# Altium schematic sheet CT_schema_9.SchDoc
size 391 x 238 mm
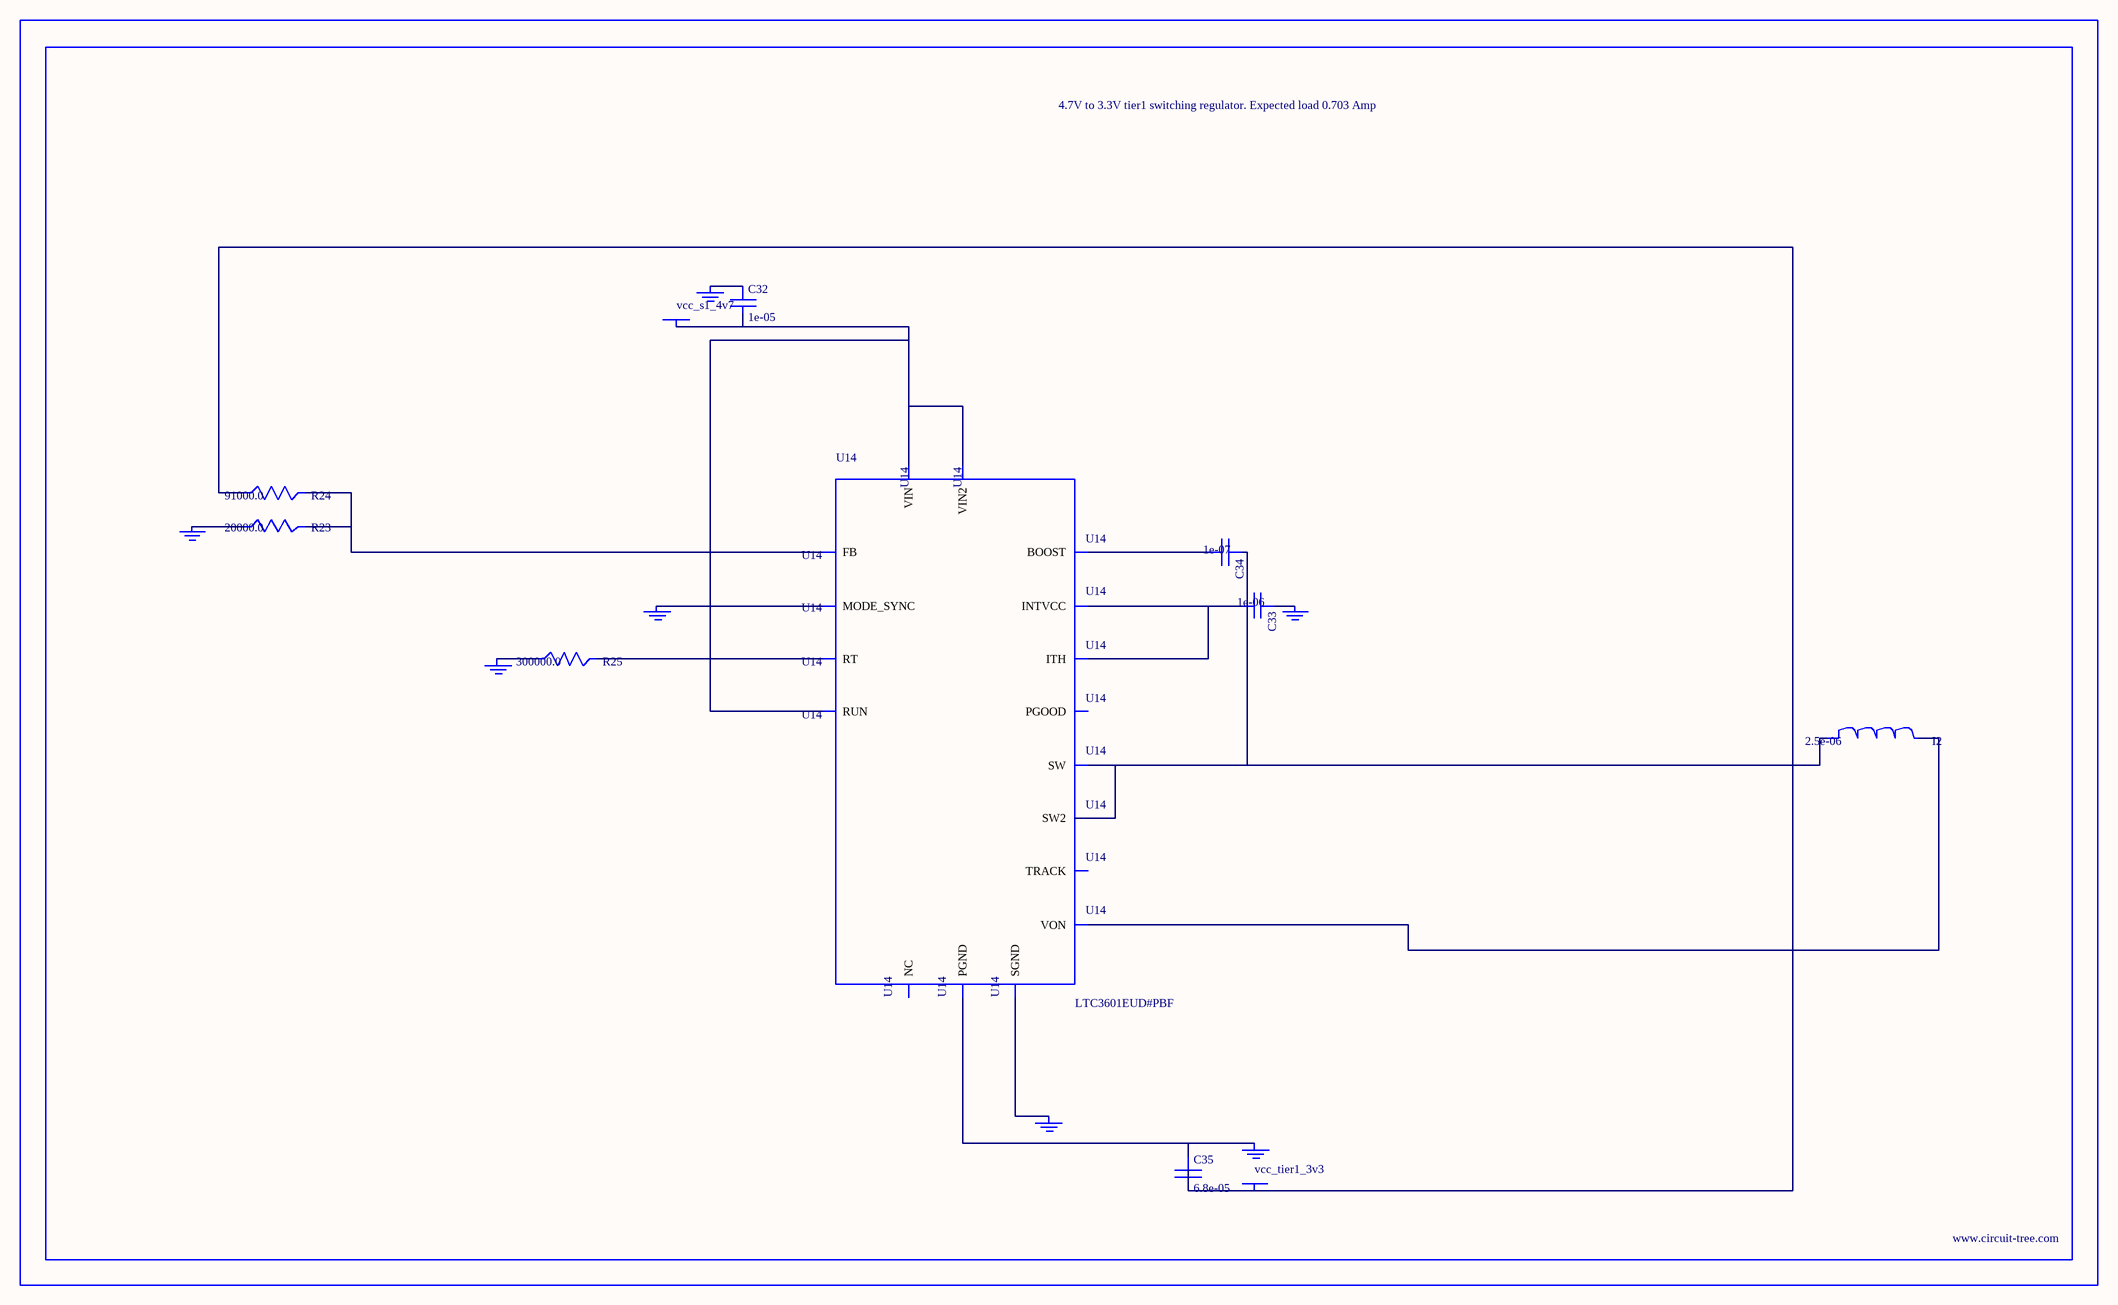
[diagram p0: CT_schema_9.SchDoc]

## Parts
BORDER8  (no value)
C32  1e-05  [C0805]
C33  1e-06  [C0603]
C34  1e-07  [C0402]
C35  6.8e-05  [2220]
GND_INSTANCE_8_0  (no value)
GND_INSTANCE_8_1  (no value)
GND_INSTANCE_8_2  (no value)
GND_INSTANCE_8_3  (no value)
GND_INSTANCE_8_4  (no value)
GND_INSTANCE_8_5  (no value)
GND_INSTANCE_8_6  (no value)
I2  2.5e-06  [DR1040]
POWER_INSTANCE_8_0  vcc_s1_4v7
POWER_INSTANCE_8_1  vcc_tier1_3v3
R23  20000.0  [R0603]
R24  91000.0  [R0603]
R25  300000.0  [R0603]
U14  LTC3601EUD#PBF  [QFN-16_EP]

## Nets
NetC32_1: C32.1 GND_INSTANCE_8_5.0(GND)
NetC32_2: C32.2 POWER_INSTANCE_8_0.0(PWR) U14.14(RUN) U14.15(VIN) U14.16(VIN2)
NetC33_1: C33.1 GND_INSTANCE_8_1.0(GND)
NetC33_2: C33.2 U14.7(INTVCC) U14.12(ITH)
NetC34_1: C34.1 I2.1 U14.3(SW) U14.4(SW2)
NetC34_2: C34.2 U14.6(BOOST)
NetC35_1: C35.1 GND_INSTANCE_8_6.0(GND) U14.17(PGND)
NetC35_2: C35.2 I2.2 POWER_INSTANCE_8_1.0(PWR) R24.1 U14.8(VON)
NetGND_INSTANCE_8_0_0: GND_INSTANCE_8_0.0(GND) U14.1(MODE_SYNC)
NetGND_INSTANCE_8_2_0: GND_INSTANCE_8_2.0(GND) U14.9(SGND)
NetGND_INSTANCE_8_3_0: GND_INSTANCE_8_3.0(GND) R25.1
NetGND_INSTANCE_8_4_0: GND_INSTANCE_8_4.0(GND) R23.1
NetR23_2: R23.2 R24.2 U14.11(FB)
NetR25_2: R25.2 U14.10(RT)

Not connected (* = marked no-connect by the designer): U14 2(PGOOD) 5(NC) 13(TRACK)

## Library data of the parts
BORDER8 = BORDER_PAGE8
C32 = C0805C106K8RACTU
C33 = C0603C105K3RACTU
C34 = C0402C104K3RACTU
C35 = C5750X5R1A686M
GND_INSTANCE_8_0-GND_INSTANCE_8_6 = GND
I2 = DR1040-2R5-R
POWER_INSTANCE_8_0 POWER_INSTANCE_8_1 = PWR
R23 = RC0603JR-0720KL
R24 = RC0603JR-0791KL
R25 = RC0603JR-07300KL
